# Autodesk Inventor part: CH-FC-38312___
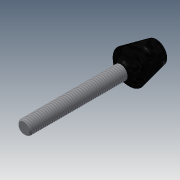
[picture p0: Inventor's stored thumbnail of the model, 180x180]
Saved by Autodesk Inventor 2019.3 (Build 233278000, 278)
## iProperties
Created: 2010-06
Part Number: CH-FC-38312___
Material: Ogólny
Document SubType Name: Modeling
Designer: CADENGINEERING4
Density: 1 g/cm^3
Appearance: Domyślna
Author: CADENGINEERING4
Revision Number: ANY
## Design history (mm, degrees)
feature "NONE"
node "Bryła1"
